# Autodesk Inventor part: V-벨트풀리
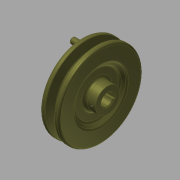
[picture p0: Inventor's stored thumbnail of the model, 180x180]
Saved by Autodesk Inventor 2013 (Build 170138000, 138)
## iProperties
Company: 한국ATC센터
Created: 2015-12
Part Number: V-벨트풀리
Document SubType Name: Modeling
Designer: mdu
Density: 7.25 g/cm^3
Mass: 594.58 g
Surface Area: 210.471 cm^2
Volume: 82.011 cm^3
Material: 주철
Author: mdu
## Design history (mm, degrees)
sketch "스케치1"
  geometry: L1 (-13, 0)-(13, 0); L2 (-13, 0)-(-13, 12.5); L3 (-13, 12.5)-(-9, 12.5); L4 (-9, 12.5)-(-9, 23); L5 (-9, 23)-(-13, 27); L6 (-13, 27)-(-13, 42.7); L7 (-13, 42.7)-(-8.325, 42.7); L8 (-8.325, 42.7)-(-5.574, 33.7); L9 (-5.574, 33.7)-(-1.426, 33.7); L10 (-1.426, 33.7)-(1.325, 42.7); L11 (1.325, 42.7)-(6, 42.7); L12 (6, 42.7)-(6, 27); L13 (6, 27)-(2, 23); L14 (2, 23)-(2, 12.5); L15 (2, 12.5)-(13, 12.5); L16 (13, 12.5)-(13, 0); L17 (-7.5, 40)-(0.5, 40); 2 further points
  constraints: 34 end point, 6 parallel, 5 collinear, 5 equal length, 4 perpendicular, 2 point on line, 1 coincident, 1 horizontal, 1 midpoint
  dimensions: "d0" = 26 distance of L1.start L1.end; "d1" = 2.7 distance between parallel lines of L7 L17; "d2" = 6.3 distance between parallel lines of L9 L17; "d3" = 8 distance of L17.start L17.end; "d4" = 34 deg angle of L10 L8; "d5" = 19 distance between parallel lines of L12 L6; "d7" = 25 diameter of L15 L1; "d8" = 46 diameter of L13.end L1; "d9" = 54 diameter of L12.end L1; "d10" = 4 distance between parallel lines of L2 L4; "d11" = 80 diameter of L17 L1
revolve "회전1" sketch "스케치1" stored, may be unused: angle "d12" = 90 deg
sketch "스케치2"
  geometry: L1 (-2, 5.657)-(-2, 7.8); L2 (-2, 7.8)-(2, 7.8); L3 (2, 7.8)-(2, 5.657); A1 r 6 centre (0, 0) between (-2, 5.657) and (2, 5.657); 1 further point
  constraints: 6 end point, 2 parallel, 2 point on circle, 1 centre point, 1 coincident, 1 perpendicular, 1 vertical
  dimensions: "d13" = 12 diameter of A1; "d14" = 13.8 dimension on A1 L2; "d15" = 4 distance of L1.end L2.end
extrude "돌출1" cut sketch "스케치2" stored distance "d16" = 10; taper "d17" = 0 deg
node "작업 평면1"
sketch "스케치3"
  geometry: L1 (-5.5, 12.5)-(-5.5, -12.5) reference; L2 (20.5, 27)-(20.5, -27) reference; 3 further points
  constraints: 1 horizontal alignment, 1 midpoint
  dimensions: "d18" = 4 distance from line of point (-1.5, 0) L1; "d33" = 22 distance from line of point (-1.5, 0) L2 (derived)
hole "구멍1" sketch "스케치3" at (-1.5, 0) diameter "d19" = 2.459; stored, may be unused: countersink angle "d23" = 90 deg, drill point angle "d25" = 118 deg; dims "d20" = 6, "d21" = 4, "d22" = 2, "d24" = 8
fillet "모깎기1" dims "d26" = 2, "d27" = 0.5, "d28" = 1, "d29" = 3
chamfer "모따기1" distance "d30" = 1; stored, may be unused: second distance "d31" = 2, angle "d32" = 45 deg
sketch "스케치4" dims "d35" = 70
  geometry: C1 r 3 at (35, 0); 2 further points
  constraints: 2 horizontal alignment, 1 centre point, 1 coincident, 2 other
  dimensions: "d34" = 6 diameter of C1
extrude "돌출2" join sketch "스케치4" distance "d36" = 10; taper "d37" = 0 deg
fillet "모깎기2" dims "d38" = 0.5, "d39" = 1
node "솔리드1"
